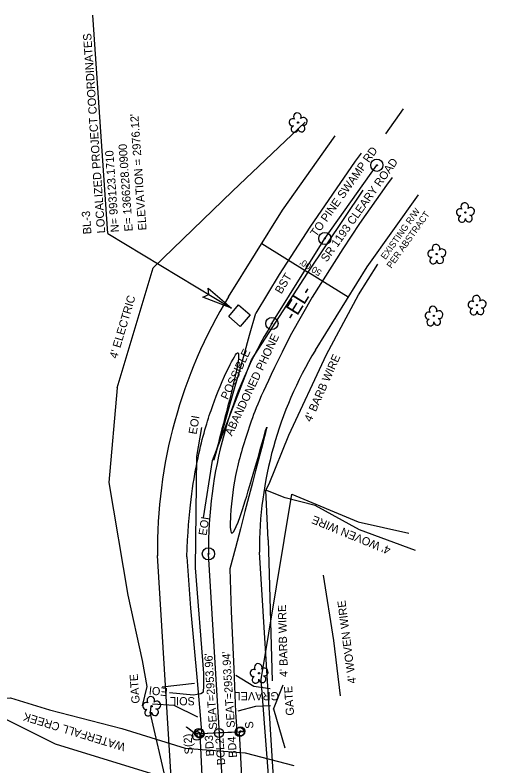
# Model space of a CAD drawing. Extents: x 1365957 to 1366704, y 992284 to 993271.
# Drawn here: x 1366118.1 to 1366353.9, y 992903 to 993270.5 of the extents above; entities that cross this region are included whole.
import ezdxf

# ---------------------------------------------------------------- set-up
doc = ezdxf.new("R2010")
doc.units = 0
for name, color, linetype in [('Cogo Default Point CELL', 7, 'Continuous'), ('COGO Default Point Elevation', 7, 'Continuous'), ('COGO Default Point Number', 7, 'Continuous'), ('CTL Supplemental Horizontal and Vertical CELL', 7, 'Continuous'), ('CTL Supplemental Horizontal and Vertical Text', 7, 'Continuous'), ('Default', 7, 'Continuous'), ('Exist Horizontal Alignment', 7, 'Continuous'), ('Exist Horizontal Alignment Direction Label', 7, 'Continuous'), ('Exist Horizontal Alignment Point', 7, 'Continuous'), ('Exist Hydro Stream or Body of Water', 7, 'Continuous'), ('Exist Hydro Stream or Body of Water Text', 7, 'Continuous'), ('Exist Other Culture Fence Line', 7, 'Continuous'), ('Exist Other Culture Fence Line Text', 7, 'Continuous'), ('Exist Other Culture Gate', 7, 'Continuous'), ('Exist Other Culture Gate Text', 7, 'Continuous'), ('Exist Other Culture Located Object CELL', 7, 'Continuous'), ('Exist Other Culture Located Object Text', 7, 'Continuous'), ('Exist Other Culture Sign CELL', 7, 'Continuous'), ('Exist Other Culture Sign Text', 7, 'Continuous'), ('Exist Right of Way Line', 7, 'Continuous'), ('Exist Right of Way Line Text', 7, 'Continuous'), ('Exist Right of Way Width CELL', 7, 'Continuous'), ('Exist Roads EOP', 7, 'Continuous'), ('Exist Roads EOP Leader', 7, 'Continuous'), ('Exist Roads EOP Text', 7, 'Continuous'), ('Exist Roads Soil', 7, 'Continuous'), ('Exist Roads Soil Text', 7, 'Continuous'), ('Exist Structure Major Bridge Seat Top Elevation', 7, 'Continuous'), ('Exist Structure Major Bridge WW', 7, 'Continuous'), ('Exist Structure Major Deck Tunnel Box Culvert', 7, 'Continuous'), ('Exist Utilities Other Unknown UG SUE', 7, 'Continuous'), ('Exist Utilities Other Unknown UG SUE Text', 7, 'Continuous'), ('Exist Vegetation Tree CELL', 7, 'Continuous'), ('Exist Vegetation Woods Line', 7, 'Continuous'), ('Old_Level_11', 7, 'Continuous')]:
    doc.layers.add(name, color=color, linetype=linetype)

# ---------------------------------------------------------------- blocks, each defined once
blk = doc.blocks.new('EXIST OTHER CULTURE LOCATED OBJECT')
at = {"layer": 'Exist Other Culture Located Object CELL'}
for radius in [0.0436, 0.0048]:
    blk.add_circle((0, 0), radius, dxfattribs=at)

msp = doc.modelspace()

# ---------------------------------------------------------------- linework, layer by layer
at = {"layer": 'Cogo Default Point CELL'}
for points in [[(1366295.16, 993196.91), (1366295.46, 993196.91)], [(1366295.46, 993197.21), (1366295.46, 993196.91)], [(1366295.46, 993196.91), (1366295.76, 993196.91)], [(1366295.46, 993196.91), (1366295.46, 993196.61)], [(1366269.69, 993161.02), (1366269.99, 993161.02)], [(1366269.99, 993161.32), (1366269.99, 993161.02)], [(1366269.99, 993161.02), (1366270.29, 993161.02)], [(1366269.99, 993161.02), (1366269.99, 993160.72)], [(1366244.06, 993119.65), (1366244.06, 993119.35)], [(1366243.76, 993119.35), (1366244.06, 993119.35)], [(1366244.06, 993119.35), (1366244.36, 993119.35)], [(1366244.06, 993119.35), (1366244.06, 993119.05)], [(1366212.6, 993006.47), (1366212.9, 993006.47)], [(1366212.9, 993006.77), (1366212.9, 993006.47)], [(1366212.9, 993006.47), (1366213.2, 993006.47)], [(1366212.9, 993006.47), (1366212.9, 993006.17)]]:
    msp.add_lwpolyline(points, dxfattribs=at)
for centre in [(1366295.46, 993196.91), (1366269.99, 993161.02), (1366244.06, 993119.35), (1366212.9, 993006.47)]:
    msp.add_circle(centre, 0.234, dxfattribs=at)
at = {"layer": 'CTL Supplemental Horizontal and Vertical CELL'}
msp.add_line((1366228.09, 993123.17), (1366228.09, 993123.17), dxfattribs=at)
msp.add_lwpolyline([(1366222.89, 993122.79), (1366227.72, 993128.42), (1366233.35, 993123.58), (1366228.52, 993117.96)], close=True, dxfattribs=at)
at = {"layer": 'Default'}
for q in [(1366156.22, 993270.54), (1366224.19, 993126.88)]:
    msp.add_line((1366163.65, 993163.45), q, dxfattribs=at)
at = {"layer": 'Exist Horizontal Alignment'}
for p, q in [((1366269.99, 993161.02), (1366295.46, 993196.91)), ((1366244.06, 993119.35), (1366269.99, 993161.02)), ((1366230.09, 992730.31), (1366212.9, 993006.47))]:
    msp.add_line(p, q, dxfattribs=at)
msp.add_arc((1366426.22, 993008.32), 213.33, 148.6372, 180.4974, dxfattribs=at)
at = {"layer": 'Exist Horizontal Alignment Point'}
for centre in [(1366295.46, 993196.91), (1366269.99, 993161.02), (1366244.06, 993119.35), (1366212.9, 993006.47)]:
    msp.add_circle(centre, 3, dxfattribs=at)
at = {"layer": 'Exist Hydro Stream or Body of Water'}
for points in [[(1366093.76, 992934.89), (1366115.88, 992935.85), (1366135.11, 992929.97)], [(1366135.11, 992929.97), (1366170.43, 992920.94), (1366201.51, 992911.21), (1366230.98, 992908.99), (1366254.85, 992902.77)], [(1366093.19, 992923.14), (1366113.57, 992925.45), (1366137.77, 992913.36), (1366201.95, 992893.6), (1366232.22, 992890.91), (1366257.57, 992885.07), (1366276.96, 992869.22), (1366301.86, 992863.77), (1366317.67, 992855.76), (1366332.55, 992843.55)]]:
    msp.add_lwpolyline(points, dxfattribs=at)
at = {"layer": 'Exist Other Culture Fence Line'}
for p, q in [((1366168.28, 993087.85), (1366185.77, 993146.71)), ((1366193.6, 992888.77), (1366184.39, 992928.95)), ((1366250.59, 992911.3), (1366244.95, 992930.3))]:
    msp.add_line(p, q, dxfattribs=at)
for points in [[(1366185.77, 993146.71), (1366224.73, 993184.2), (1366260.41, 993218.06)], [(1366242.17, 993013.32), (1366241, 993037.63), (1366242.66, 993040.75), (1366252.34, 993064.7), (1366270.87, 993104.18), (1366286.43, 993133.4), (1366296.03, 993148.5)], [(1366168.28, 993087.85), (1366164.14, 993041.39)], [(1366164.14, 993041.39), (1366173.41, 992986.15), (1366180.46, 992954.12), (1366182.73, 992941.39)], [(1366265.18, 993030.09), (1366250.48, 993033.92), (1366241, 993037.63)], [(1366314.47, 993008.15), (1366286.92, 993018.29), (1366265.18, 993030.09)], [(1366242.17, 993013.32), (1366242.67, 992996.56), (1366244.16, 992944.16)], [(1366277.65, 992936.93), (1366274.35, 992963.96), (1366269.25, 992996.04)], [(1366184.72, 992931.87), (1366184.39, 992928.95)]]:
    msp.add_lwpolyline(points, dxfattribs=at)
at = {"layer": 'Exist Other Culture Gate'}
msp.add_line((1366244.9, 992930.42), (1366249.5, 992942.29), dxfattribs=at)
msp.add_lwpolyline([(1366182.73, 992941.39), (1366180.45, 992931.93)], dxfattribs=at)
at = {"layer": 'Exist Other Culture Sign CELL'}
for centre, radius in [((1366228.65, 992919.49), 2.18), ((1366207.22, 992917.25), 2.18), ((1366208.29, 992918.76), 2.18), ((1366207.22, 992917.25), 0.24), ((1366208.29, 992918.76), 0.24), ((1366228.65, 992919.49), 0.24)]:
    msp.add_circle(centre, radius, dxfattribs=at)
at = {"layer": 'Exist Right of Way Line'}
for p, q in [((1366249.16, 993174.87), (1366275.07, 993211.37)), ((1366290.81, 993147.16), (1366315.85, 993182.44)), ((1366222.77, 993132.47), (1366249.16, 993174.87)), ((1366265.35, 993106.25), (1366290.81, 993147.16)), ((1366255.03, 992732.11), (1366237.89, 993007.34)), ((1366205.16, 992728.51), (1366187.91, 993005.57))]:
    msp.add_line(p, q, dxfattribs=at)
for radius, start, end in [(238.33, 148.6085, 180.6626), (188.33, 148.6713, 180.3002)]:
    msp.add_arc((1366426.22, 993008.32), radius, start, end, dxfattribs=at)
at = {"layer": 'Exist Right of Way Width CELL'}
for p in [(1366239.04, 993158.6), (1366281.49, 993132.19)]:
    msp.add_line(p, (1366261.62, 993144.55), dxfattribs=at)
at = {"layer": 'Exist Roads EOP'}
for points in [[(1366287.82, 993202.77), (1366284.9, 993198.89), (1366262.58, 993166.49), (1366247.55, 993143.29), (1366236.15, 993124.37)], [(1366302.99, 993190.92), (1366300.17, 993187.17), (1366287.05, 993168.32), (1366278.79, 993155.98), (1366263.85, 993132.18), (1366253.65, 993114.39)], [(1366202.29, 993004.98), (1366204.14, 992979.89), (1366207.34, 992944.24)], [(1366223.45, 992999.11), (1366224.06, 992978.15)], [(1366224.06, 992978.15), (1366225.37, 992950.15), (1366226.22, 992928.84), (1366226.86, 992919.57), (1366226.88, 992919.16)], [(1366207.34, 992944.24), (1366208.89, 992927.48), (1366209.53, 992919.01), (1366209.52, 992919.03), (1366209.55, 992918.41)], [(1366209.55, 992918.41), (1366218.09, 992918.96), (1366226.88, 992919.16)]]:
    msp.add_lwpolyline(points, dxfattribs=at)
for points in [[(1366202.29, 993004.98), (1366203.33, 993028.26), (1366207.21, 993054.1), (1366214.36, 993078.19), (1366220.61, 993093.77), (1366236.15, 993124.37), (1366202.29, 993004.98), (1366236.15, 993124.37)], [(1366253.65, 993114.39), (1366240.25, 993088.05), (1366233.48, 993071.46), (1366226.12, 993047.22), (1366223.3, 993026.1), (1366223.45, 992999.11), (1366253.65, 993114.39), (1366223.45, 992999.11)]]:
    msp.add_open_spline(points, degree=3, dxfattribs=at)
at = {"layer": 'Exist Roads EOP Leader'}
msp.add_lwpolyline([(1366308.43, 993224.5), (1366299.78, 993212.32)], dxfattribs=at)
at = {"layer": 'Exist Roads Soil'}
msp.add_line((1366190.24, 992941.24), (1366206.13, 992943.15), dxfattribs=at)
for points in [[(1366226.35, 992947.02), (1366235.13, 992941.57), (1366243.13, 992940.45)], [(1366207.7, 992926.48), (1366196.17, 992932.07), (1366185.56, 992932.86)], [(1366243.37, 992931.93), (1366236.03, 992931.72), (1366227.37, 992929.43)]]:
    msp.add_lwpolyline(points, dxfattribs=at)
at = {"layer": 'Exist Structure Major Bridge WW'}
msp.add_line((1366202.24, 992921.68), (1366206.46, 992918.39), dxfattribs=at)
for points in [[(1366206.21, 992918.38), (1366202.11, 992921.58), (1366202.24, 992921.68)], [(1366207.85, 992918.43), (1366206.09, 992918.26), (1366206.09, 992918.07), (1366207.97, 992918.23)], [(1366229.01, 992919.52), (1366230.42, 992919.51), (1366230.37, 992919.24), (1366229.06, 992919.23)]]:
    msp.add_lwpolyline(points, dxfattribs=at)
at = {"layer": 'Exist Structure Major Deck Tunnel Box Culvert'}
for p, q in [((1366228.24, 992919.11), (1366208.71, 992918.26)), ((1366208.71, 992918.26), (1366210.62, 992878.44)), ((1366230.2, 992879.2), (1366228.24, 992919.11))]:
    msp.add_line(p, q, dxfattribs=at)
at = {"layer": 'Exist Utilities Other Unknown UG SUE'}
for points in [[(1366210.55, 993024.04), (1366214.94, 993052.29), (1366234.02, 993101.6), (1366261.53, 993144.02), (1366288.84, 993184.62)], [(1366193.79, 992938.49), (1366205.56, 992937.37), (1366209.14, 992937.95), (1366210.44, 992938.89), (1366210.66, 992941.57), (1366210.74, 992947.99), (1366206.62, 992999.55), (1366207.21, 993054.13), (1366209.71, 993068.31)]]:
    msp.add_lwpolyline(points, dxfattribs=at)
at = {"layer": 'Exist Vegetation Tree CELL'}
for p, q in [((1366256.89, 993217.84), (1366256.89, 993217.84)), ((1366338.89, 993173.75), (1366338.89, 993173.75)), ((1366324.83, 993153.38), (1366324.83, 993153.38)), ((1366344.61, 993128.35), (1366344.61, 993128.35)), ((1366323.41, 993123.06), (1366323.41, 993123.06)), ((1366237.73, 992947.93), (1366237.73, 992947.93)), ((1366185.08, 992931.78), (1366185.08, 992931.78))]:
    msp.add_line(p, q, dxfattribs=at)
for centre in [(1366256.89, 993217.84), (1366338.89, 993173.75), (1366324.83, 993153.38), (1366344.61, 993128.35), (1366323.41, 993123.06), (1366237.73, 992947.93), (1366185.08, 992931.78)]:
    msp.add_circle(centre, 0.326, dxfattribs=at)
for centre, radius, start, end in [((1366256.5, 993220.71), 1.86, 330.1651, 219.7134), ((1366254.28, 993217.99), 1.73, 62.6636, 279.3457), ((1366259.44, 993218.43), 1.9, 257.1011, 134.1999), ((1366255.18, 993214.72), 1.69, 111.5671, 6.231), ((1366258.56, 993214.94), 1.7, 181.2822, 74.56), ((1366338.51, 993176.62), 1.86, 330.1651, 219.7134), ((1366336.29, 993173.9), 1.73, 62.6636, 279.3457), ((1366341.44, 993174.34), 1.9, 257.1011, 134.1999), ((1366337.19, 993170.63), 1.69, 111.5671, 6.231), ((1366340.57, 993170.85), 1.7, 181.2822, 74.56), ((1366324.45, 993156.26), 1.86, 330.1651, 219.7134), ((1366322.23, 993153.54), 1.73, 62.6636, 279.3457), ((1366327.38, 993153.97), 1.9, 257.1011, 134.1999), ((1366323.13, 993150.26), 1.69, 111.5671, 6.231), ((1366326.51, 993150.48), 1.7, 181.2822, 74.56), ((1366344.23, 993131.23), 1.86, 330.1651, 219.7134), ((1366347.16, 993128.94), 1.9, 257.1011, 134.1999), ((1366323.03, 993125.93), 1.86, 330.1651, 219.7134), ((1366342, 993128.51), 1.73, 62.6636, 279.3457), ((1366346.28, 993125.45), 1.7, 181.2822, 74.56), ((1366320.81, 993123.21), 1.73, 62.6636, 279.3457), ((1366325.96, 993123.65), 1.9, 257.1011, 134.1999), ((1366342.91, 993125.23), 1.69, 111.5671, 6.231), ((1366321.71, 993119.94), 1.69, 111.5671, 6.231), ((1366325.08, 993120.16), 1.7, 181.2822, 74.56), ((1366237.35, 992950.81), 1.86, 330.1651, 219.7134), ((1366235.13, 992948.09), 1.73, 62.6636, 279.3457), ((1366240.28, 992948.52), 1.9, 257.1011, 134.1999), ((1366236.03, 992944.81), 1.69, 111.5671, 6.231), ((1366239.4, 992945.03), 1.7, 181.2822, 74.56), ((1366184.69, 992934.65), 1.86, 330.1651, 219.7134), ((1366182.47, 992931.93), 1.73, 62.6636, 279.3457), ((1366187.63, 992932.37), 1.9, 257.1011, 134.1999), ((1366183.37, 992928.66), 1.69, 111.5671, 6.231), ((1366186.75, 992928.88), 1.7, 181.2822, 74.56)]:
    msp.add_arc(centre, radius, start, end, dxfattribs=at)
at = {"layer": 'Exist Vegetation Woods Line'}
msp.add_lwpolyline([(1366353.88, 992749.61), (1366286.45, 992746.68), (1366276.2, 992809.35), (1366247.3, 992833.98), (1366238.78, 992944.89), (1366253.73, 993035.73), (1366286.36, 993022.08), (1366311.15, 993016.52)], dxfattribs=at)
at = {"layer": 'Old_Level_11'}
msp.add_lwpolyline([(1366212.88, 993136.68), (1366224.19, 993126.88), (1366210.15, 993132.3), (1366213.11, 993133.57)], close=True, dxfattribs=at)

# ---------------------------------------------------------------- block references
at = {"layer": 'Exist Other Culture Located Object CELL', "xscale": 50, "yscale": 49.99999999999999, "rotation": -9.144643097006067}
for p in [(1366218.12, 992918.69), (1366228.24, 992919.11), (1366208.71, 992918.26)]:
    msp.add_blockref('EXIST OTHER CULTURE LOCATED OBJECT', p, dxfattribs=at)

# ---------------------------------------------------------------- texts
at = {"layer": 'COGO Default Point Elevation'}
for p in [(1366295.71, 993196.78), (1366270.24, 993160.89), (1366244.31, 993119.23), (1366213.15, 993006.35)]:
    msp.add_text('0.00', height=0.25, dxfattribs=at).set_placement(p)
at = {"layer": 'COGO Default Point Number'}
for s, p in [('10', (1366295.71, 993197.16)), ('9', (1366270.24, 993161.27)), ('8', (1366244.31, 993119.6)), ('7', (1366213.15, 993006.72))]:
    msp.add_text(s, height=0.25, dxfattribs=at).set_placement(p)
at = {"layer": 'CTL Supplemental Horizontal and Vertical Text'}
for s, p in [('LOCALIZED PROJECT COORDINATES', (1366162.37, 993163.7)), ("ELEVATION = 2976.12'", (1366182.6, 993165.12)), ('E= 1366228.0900', (1366175.86, 993164.65)), ('N= 993123.1710', (1366169.12, 993164.17)), ('BL-3', (1366155.63, 993163.22))]:
    msp.add_text(s, height=4.055, rotation=94.0364, dxfattribs=at).set_placement(p)
at = {"layer": 'Exist Horizontal Alignment Direction Label'}
msp.add_text('-EL-  ', height=7, rotation=58.1059, dxfattribs=at).set_placement((1366254.85, 993120.25))
at = {"layer": 'Exist Hydro Stream or Body of Water Text'}
msp.add_text('WATERFALL CREEK', height=4, rotation=162.885, dxfattribs=at).set_placement((1366172.58, 992913.48))
at = {"layer": 'Exist Other Culture Fence Line Text'}
for s, height, rotation, p in [("4' ELECTRIC", 4, 73.4566, (1366168.14, 993101.86)), ("4' BARB WIRE", 3.9936, 65.9839, (1366263.3, 993070.79)), ("4' WOVEN WIRE", 3.9936, 157.6091, (1366302.6, 993009.69)), ("4' WOVEN WIRE", 3.9936, 97.3991, (1366285.34, 992943.14)), ("4' BARB WIRE", 3.9936, 91.5082, (1366251.88, 992946.14))]:
    msp.add_text(s, height=height, rotation=rotation, dxfattribs=at).set_placement(p)
at = {"layer": 'Exist Other Culture Gate Text'}
for p in [(1366179.26, 992933.23), (1366254.95, 992927.33)]:
    msp.add_text('GATE', height=4, rotation=93.9691, dxfattribs=at).set_placement(p)
at = {"layer": 'Exist Other Culture Located Object Text'}
for s, p in [('BD3', (1366215.75, 992907.36)), ('BCL2', (1366221.19, 992903.01)), ('BD4', (1366226.93, 992906.66))]:
    msp.add_text(s, height=4, rotation=93.7143, dxfattribs=at).set_placement(p)
at = {"layer": 'Exist Other Culture Sign Text'}
for s, p in [('S', (1366235.03, 992920.93)), ('S(2)', (1366205.33, 992908.35))]:
    msp.add_text(s, height=4, rotation=93.9691, dxfattribs=at).set_placement(p)
at = {"layer": 'Exist Right of Way Line Text'}
for s, p in [('EXISTING R/W', (1366299.74, 993150.41)), ('PER ABSTRACT', (1366302.59, 993146.13))]:
    msp.add_text(s, height=3.2, rotation=54.6343, dxfattribs=at).set_placement(p)
at = {"layer": 'Exist Right of Way Width CELL'}
msp.add_text("50.00'", height=3.2, rotation=148.1059, dxfattribs=at).set_placement((1366268.78, 993145.09))
at = {"layer": 'Exist Roads EOP Text'}
for s, rotation, p in [('TO PINE SWAMP RD', 54.6343, (1366265.78, 993161.53)), ('SR 1193 CLEARY ROAD', 54.6343, (1366270.93, 993149.17)), ('BST', 58.9353, (1366248.67, 993133.53))]:
    msp.add_text(s, height=4, rotation=rotation, dxfattribs=at).set_placement(p)
at = {"layer": 'Exist Roads Soil Text'}
for s, p in [('SOIL', (1366206.31, 992936.24)), ('GRAVEL', (1366247.47, 992938.69))]:
    msp.add_text(s, height=4, rotation=180, dxfattribs=at).set_placement(p)
at = {"layer": 'Exist Structure Major Bridge Seat Top Elevation'}
for s, p in [("SEAT=2953.94'", (1366225.94, 992921.38)), ("SEAT=2953.96'", (1366217.23, 992920.44))]:
    msp.add_text(s, height=4, rotation=93.678, dxfattribs=at).set_placement(p)
at = {"layer": 'Exist Utilities Other Unknown UG SUE Text'}
for s, rotation, p in [('ABANDONED PHONE', 64.6397, (1366224.41, 993063.94)), ('POSSIBLE', 64.6397, (1366222.35, 993081.71)), ('EOI', 80.034, (1366207.06, 993064.79)), ('EOI', 81.1685, (1366211.98, 993015.23)), ('EOI', 174.5868, (1366193.13, 992940.68))]:
    msp.add_text(s, height=4, rotation=rotation, dxfattribs=at).set_placement(p)

doc.saveas('drawing.dxf')
